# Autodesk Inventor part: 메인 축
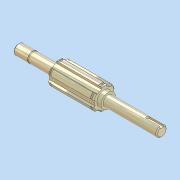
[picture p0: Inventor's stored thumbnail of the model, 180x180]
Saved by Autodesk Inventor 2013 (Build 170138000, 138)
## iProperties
Company: 한국ATC센터
Created: 2014-07
Part Number: 메인 축
Document SubType Name: 모델링
Designer: KYOUNG IL JANG
Mass: 21.4462 g
Surface Area: 72.5109 cm^2
Volume: 21.4462 cm^3
Density: 1 g/cm^3
Material: Generic
변환 표준: STEP AP214IS
파일 이름: C:\Users\SeoGD\Desktop\?쒗뿕\硫붿씤 異?.stp
전처리기: Build: 253, Release: 2010 SP1 - Date: Wed 07/29/2009
전송 단위: 밀리미터
불확실성: 0.01
Author: KYOUNG IL JANG
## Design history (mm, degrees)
revolve "회전1" stored, may be unused: angle "d10" = 90 deg
sketch "스케치2"
  geometry: L1 (2.5, 10.712)-(2.5, 8.646); L2 (-2.5, 10.712)-(-2.5, 8.646); A1 r 9 centre (0, 0) between (2.5, 8.646) and (-2.5, 8.646) reference; A2 r 11 centre (0, 0) between (2.5, 10.712) and (-2.5, 10.712); 1 further point
  constraints: 4 end point, 4 point on circle, 2 parallel, 1 centre point, 1 coincident, 1 vertical
  dimensions: "d11" = 22 diameter of A2; "d12" = 5 distance between parallel lines of L1 L2
extrude "돌출1" join sketch "스케치2" stored distance "d13" = 10; taper "d14" = 0 deg
chamfer "모따기1" distance "d15" = 1; stored, may be unused: second distance "d16" = 2, angle "d17" = 45 deg
node "작업 평면1"
node "작업 평면2"
sketch "스케치3"
  geometry: L1 (2.5, 10.712)-(2.5, 10.198); L2 (-2.5, 10.712)-(-2.5, 10.198); A1 r 11 centre (0, 0) between (2.5, 10.712) and (-2.5, 10.712) reference; A2 r 10.5 centre (0, 0) between (2.5, 10.198) and (-2.5, 10.198); 1 further point
  constraints: 4 end point, 2 point on circle, 1 centre point, 1 coincident, 1 parallel, 1 vertical
  dimensions: "d19" = 21 diameter of A2
extrude "돌출2" cut sketch "스케치3" distance "d20" = 1.35; taper "d21" = 0 deg
node "작업 평면3"
sketch "스케치4"
  geometry: L1 (-26, -5)-(-26, 5) reference; L2 (-26, 1.5)-(-12.5, 1.5); L3 (-12.5, -1.5)-(-26, -1.5); A1 r 1.5 centre (-12.5, 0) between (-12.5, -1.5) and (-12.5, 1.5); 2 further points
  constraints: 4 end point, 2 perpendicular, 2 point on circle, 2 point on line, 2 tangent, 1 centre point, 1 horizontal alignment, 1 midpoint
  dimensions: "d25" = 3 distance between parallel lines of L3 L2; "d26" = 15 dimension on A1 L1
extrude "돌출3" cut sketch "스케치4" distance "d27" = 1.8; taper "d28" = 0 deg
chamfer "모따기2" distance "d29" = 1; stored, may be unused: second distance "d30" = 2, angle "d31" = 45 deg
node "솔리드1"
node "솔리드 본체"
node "곡면 본체"
mirror "대칭1"
pattern_circular "원형 패턴1" dims "d23" = 360 deg
sketch "스케치1"
  geometry: L1 (-69.5, 0)-(69.5, 0); L2 (69.5, 0)-(69.5, 5); L3 (69.5, 5)-(55.5, 5); L4 (55.5, 5)-(55.5, 4.8); L5 (55.5, 4.8)-(54.35, 4.8); L6 (54.35, 4.8)-(54.35, 5); L7 (54.35, 5)-(30.5, 5); L8 (30.5, 5)-(30.5, 9); L9 (30.5, 9)-(-13.5, 9); L10 (-13.5, 9)-(-13.5, 7); L11 (-13.5, 7)-(-17.5, 7); L12 (-17.5, 7)-(-17.5, 5); L13 (-17.5, 5)-(-69.5, 5); L14 (-69.5, 5)-(-69.5, 0); 2 further points
  constraints: 28 end point, 9 parallel, 4 collinear, 2 perpendicular, 1 coincident, 1 horizontal, 1 midpoint
  dimensions: "d2" = 1.15 distance between parallel lines of L6 L4; "d3" = 10 diameter of L3 L1; "d4" = 9.6 diameter of L5 L1; "d6" = 44 distance between parallel lines of L10 L8; "d7" = 4 distance between parallel lines of L12 L10; "d8" = 14 diameter of L11 L1; "d9" = 18 diameter of L9 L1; "d33" = 52 distance from line of L12.end L14; "d37" = 39 distance between parallel lines of L8 L2; "d38" = 14 distance between parallel lines of L2 L4
node "솔리드2"
other parameters: "d18" = -1.65
